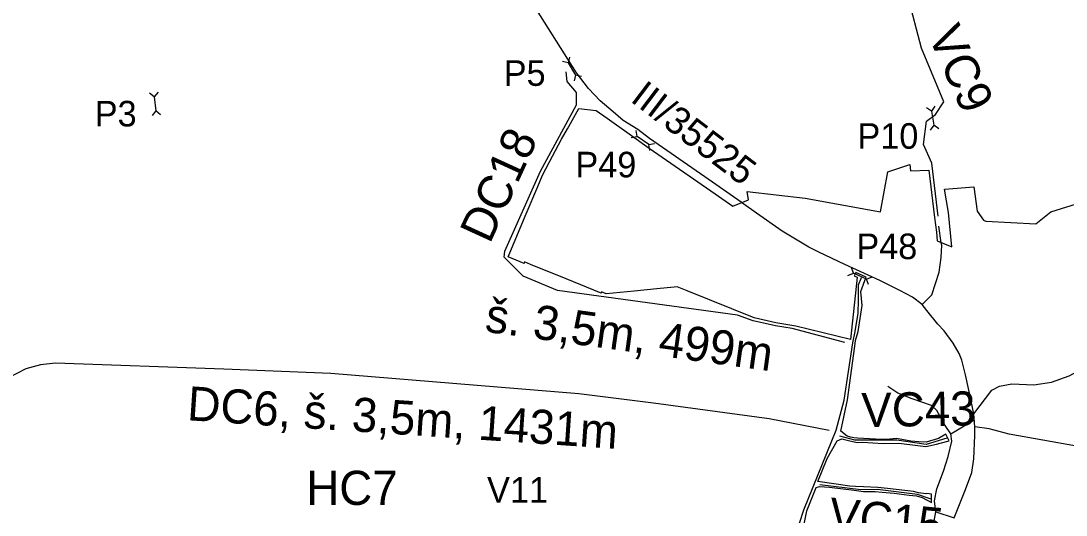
# Model space of a CAD drawing. Extents: x -638669 to -632369, y -1091026 to -1088056.
# Drawn here: x -636112 to -635193, y -1089141 to -1088706 of the extents above; entities that cross this region are included whole.
import ezdxf

# ---------------------------------------------------------------- set-up
doc = ezdxf.new("R2010")
doc.units = 0
for name, color, linetype in [('01_DOPRAVA', 7, 'Continuous'), ('01_DOPRAVA_MIMO_OBVOD', 7, 'Continuous'), ('01_OBVOD PÚ', 7, 'Continuous'), ('03_PC_NÁVRH', 7, 'Continuous'), ('03_PC_OBJEKTY_NÁVRH', 7, 'Continuous'), ('03_PC_OBJEKTY_STAV', 7, 'Continuous'), ('03_PC_POPIS_NÁVRH', 7, 'Continuous'), ('03_PC_POPIS_STAV', 7, 'Continuous'), ('03_PC_STAV', 7, 'Continuous')]:
    doc.layers.add(name, color=color, linetype=linetype)

msp = doc.modelspace()

# ---------------------------------------------------------------- linework, layer by layer
at = {"layer": '01_DOPRAVA'}
for points in [[(-635644.66, -1088718.58), (-635665.58, -1088684.91), (-635674.3, -1088665.29), (-635680.03, -1088638.99), (-635693.11, -1088583.35), (-635700.34, -1088549.68), (-635708.54, -1088514.84), (-635709.97, -1088510.03)], [(-635478.23, -1088866.19), (-635478.71, -1088865.85), (-635510.61, -1088843.52), (-635559.33, -1088809.76), (-635569.65, -1088801.76), (-635582.36, -1088793.88), (-635591.28, -1088786.39), (-635602.56, -1088776.58), (-635612.94, -1088765.82), (-635623.33, -1088751.99), (-635644.66, -1088718.58)], [(-635302.67, -1088901.38), (-635304.79, -1088886.79)]]:
    msp.add_lwpolyline(points, dxfattribs=at)
at = {"layer": '01_DOPRAVA_MIMO_OBVOD'}
for points in [[(-635291.33, -1089143.24), (-635281.53, -1089118.45), (-635275.76, -1089103.47), (-635273.99, -1089091.46), (-635273.18, -1089070.9), (-635273.18, -1089063.45), (-635274.09, -1089051.83), (-635278.86, -1089029.62), (-635281.31, -1089017.61), (-635284.6, -1089004.63), (-635287.12, -1088998.89), (-635292.13, -1088989.85), (-635300.32, -1088979.01), (-635305.81, -1088973), (-635315.3, -1088961.05), (-635319.43, -1088955.73), (-635328.1, -1088949.4), (-635339.09, -1088943.42), (-635356.73, -1088934.6), (-635387.5, -1088920.52), (-635410.49, -1088909.59), (-635419.19, -1088905.26), (-635442.61, -1088891.38), (-635465.19, -1088875.48), (-635478.23, -1088866.19)], [(-635319.43, -1088955.73), (-635311.13, -1088947.31), (-635304.64, -1088927.34), (-635302.92, -1088914.37), (-635302.33, -1088903.69), (-635302.67, -1088901.38)], [(-635274.09, -1089051.83), (-635258.33, -1089031.16), (-635251.47, -1089027.62), (-635240.71, -1089025.61), (-635221.23, -1089026.26), (-635205.73, -1089024.13), (-635190.13, -1089018.41), (-635176.86, -1089011.04), (-635164.81, -1089001.81), (-635156.09, -1088993.24), (-635156.01, -1088993.12)], [(-635294.21, -1089069.4), (-635299.21, -1089062.14), (-635306.66, -1089048.94), (-635311.32, -1089044.61), (-635328.18, -1089038.64), (-635340.93, -1089033.8), (-635349.77, -1089027.84)], [(-635307.37, -1089138.23), (-635308.66, -1089128.55), (-635306.52, -1089117.89), (-635300.88, -1089102.45), (-635296.56, -1089089.37), (-635293.4, -1089075.96), (-635294.21, -1089069.4), (-635273.66, -1089057.3)], [(-635145.56, -1089082.78), (-635169.21, -1089082.73), (-635183.95, -1089080.47), (-635243.03, -1089069.9), (-635260.61, -1089065.14), (-635273.18, -1089063.45)], [(-635338.07, -1089252.85), (-635335.26, -1089238.13), (-635335.41, -1089227.97), (-635332.77, -1089214.03), (-635328.47, -1089200.51), (-635317.9, -1089179.19), (-635314.6, -1089170.56), (-635310.08, -1089152.59), (-635307.37, -1089138.23), (-635291.33, -1089143.24)]]:
    msp.add_lwpolyline(points, dxfattribs=at)
at = {"layer": '01_OBVOD PÚ'}
msp.add_lwpolyline([(-635426.92, -1089166.93), (-635420.92, -1089137.3), (-635412.69, -1089116.75), (-635409.74, -1089115.9), (-635401.11, -1089116.43), (-635379.29, -1089119.09), (-635371.05, -1089120.1), (-635360.9, -1089120.25), (-635354.71, -1089120.84), (-635344.13, -1089121.62), (-635330.91, -1089123.51), (-635324.56, -1089124.1), (-635319.45, -1089125.46), (-635311.18, -1089129.84), (-635311.31, -1089122.66), (-635313.23, -1089122.32), (-635315.71, -1089121.92), (-635316.31, -1089122.4), (-635322.65, -1089121.39), (-635327.26, -1089120.31), (-635349.94, -1089117.72), (-635358.63, -1089116.73), (-635371.04, -1089116.17), (-635378.09, -1089115.85), (-635383.25, -1089115.49), (-635411.38, -1089111.54), (-635402.9, -1089091.33), (-635394.3, -1089075.77), (-635390.24, -1089073.88), (-635384.18, -1089075.32), (-635376.54, -1089077.13), (-635371.84, -1089076.96), (-635353.75, -1089077.9), (-635340.18, -1089077.61), (-635323.29, -1089079.74), (-635316.25, -1089080.62), (-635306.86, -1089078.63), (-635303.6, -1089077.73), (-635295.64, -1089075.55), (-635298.64, -1089069.81), (-635305.27, -1089073.56), (-635315.88, -1089076.79), (-635322.39, -1089076.54), (-635329.42, -1089075.89), (-635341.99, -1089073.71), (-635350.84, -1089074.53), (-635355.38, -1089074.38), (-635376.39, -1089073.41), (-635379.59, -1089073.05), (-635382.56, -1089072.41), (-635385.51, -1089071.48), (-635391.17, -1089067.12), (-635385.06, -1089039.5), (-635378.75, -1088992.32), (-635378.08, -1088987.33), (-635375.83, -1088979.61), (-635372.22, -1088956.67), (-635373.37, -1088944.35), (-635369.95, -1088934.7), (-635368.8, -1088931.63), (-635377.78, -1088927.53), (-635379.28, -1088930.46), (-635376.55, -1088931.71), (-635382.41, -1088986.58), (-635430.69, -1088974.75), (-635448.2, -1088971.89), (-635467.36, -1088967.38), (-635526.12, -1088943.83), (-635534.98, -1088940.28), (-635537.46, -1088940.48), (-635552.7, -1088941.96), (-635572.59, -1088943.89), (-635597.21, -1088946.28), (-635601.37, -1088944.58), (-635601.82, -1088945.69), (-635632.55, -1088933.25), (-635663.85, -1088920.58), (-635669.13, -1088918.22), (-635669.47, -1088919.73), (-635683.6, -1088913.78), (-635678.26, -1088901.16), (-635672.92, -1088888.54), (-635667.69, -1088876.16), (-635657.41, -1088851.85), (-635653.23, -1088841.98), (-635644.46, -1088825.42), (-635636.55, -1088810.49), (-635631.43, -1088801.39), (-635630.22, -1088799.23), (-635621.38, -1088783.51), (-635606.09, -1088785.18), (-635596.56, -1088792.01), (-635577.16, -1088805.79), (-635559.56, -1088818.16), (-635501.46, -1088858.56), (-635486.01, -1088869.3), (-635472.31, -1088863.82), (-635473.26, -1088856.28), (-635422.33, -1088862.1), (-635356.23, -1088874.39), (-635349.74, -1088839.03), (-635330.3, -1088832.56), (-635329.77, -1088838.1), (-635313.7, -1088837.72), (-635308.78, -1088879.13), (-635306.93, -1088892.22), (-635306.36, -1088899.9), (-635293.39, -1088905.1), (-635296.45, -1088874.7), (-635299.78, -1088854.26), (-635274.21, -1088852.38), (-635271.17, -1088873.6), (-635265.61, -1088881.69), (-635263.41, -1088882.51), (-635219.71, -1088884.85), (-635206.48, -1088874.38), (-635179.11, -1088865.65)], dxfattribs=at)
at = {"layer": '03_PC_NÁVRH'}
for points in [[(-635548.27, -1089483.24), (-635540.38, -1089456.77), (-635533.44, -1089442.45), (-635516.92, -1089414.03), (-635511.3, -1089401.47), (-635501.57, -1089371.31), (-635494.01, -1089341.69), (-635489.33, -1089317.95), (-635484.41, -1089308.94), (-635479.38, -1089302.71), (-635457.02, -1089283.85), (-635450.2, -1089272.94), (-635445.04, -1089242.94), (-635427.35, -1089147.99), (-635423.68, -1089136.34), (-635395.14, -1089066.39), (-635387.97, -1089039.81), (-635380.37, -1088989.45), (-635378.51, -1088979.5), (-635375.81, -1088963.45), (-635375.41, -1088952.35), (-635375.42, -1088938.55), (-635372.9, -1088932.07)], [(-635297.96, -1089073.28), (-635316.05, -1089078.74), (-635341.9, -1089075.19), (-635378.69, -1089075.05), (-635392.05, -1089071.41)], [(-635311.72, -1089126.86), (-635323.56, -1089122.98), (-635358.79, -1089118.46), (-635373.55, -1089118.83), (-635409.58, -1089114.49)]]:
    msp.add_lwpolyline(points, dxfattribs=at)
at = {"layer": '03_PC_OBJEKTY_NÁVRH'}
for points in [[(-635384.84, -1088930.13), (-635379.88, -1088928.24), (-635381.77, -1088923.29)], [(-635368.48, -1088933.35), (-635379.88, -1088928.24)], [(-635366.59, -1088938.31), (-635368.48, -1088933.35), (-635363.52, -1088931.46)]]:
    msp.add_lwpolyline(points, dxfattribs=at)
at = {"layer": '03_PC_OBJEKTY_STAV'}
for points in [[(-635629.45, -1088738.14), (-635630.71, -1088743.29), (-635635.86, -1088742.03)], [(-635630.71, -1088743.29), (-635624.22, -1088753.97)], [(-635619.06, -1088755.23), (-635624.22, -1088753.97), (-635625.47, -1088759.12)], [(-635991.32, -1088768.96), (-635994.65, -1088773.09), (-635998.78, -1088769.77)], [(-635994.65, -1088773.09), (-635993.3, -1088785.52)], [(-635308.34, -1088781.45), (-635311.41, -1088785.77), (-635315.74, -1088782.71)], [(-635989.17, -1088788.85), (-635993.3, -1088785.52), (-635996.63, -1088789.65)], [(-635311.41, -1088785.77), (-635309.31, -1088798.09)], [(-635575.4, -1088808.8), (-635570.17, -1088807.9), (-635571.07, -1088802.67)], [(-635304.98, -1088801.16), (-635309.31, -1088798.09), (-635312.38, -1088802.42)], [(-635559.95, -1088815.1), (-635570.17, -1088807.9)], [(-635559.05, -1088820.33), (-635559.95, -1088815.1), (-635554.73, -1088814.2)]]:
    msp.add_lwpolyline(points, dxfattribs=at)
at = {"layer": '03_PC_STAV'}
for points in [[(-635305.52, -1088878.04), (-635311.02, -1088831.43), (-635318.27, -1088815.03), (-635315.85, -1088794.53), (-635307.76, -1088788.74), (-635300.37, -1088777.56), (-635320.14, -1088730.38), (-635332.25, -1088684.22)], [(-635387.45, -1088989.27), (-635433.89, -1088976.97), (-635448.48, -1088974.6), (-635468.24, -1088970.05), (-635481.79, -1088965.04), (-635640.15, -1088943.51), (-635670.28, -1088930.72), (-635687.17, -1088914.25), (-635686.33, -1088908.91), (-635655.19, -1088838.56), (-635623.29, -1088780.2), (-635623.42, -1088769.39), (-635631.5, -1088759.72), (-635632.55, -1088751.14)], [(-635401.37, -1089066.59), (-635454.01, -1089056.2), (-635555.74, -1089042.48), (-635621.42, -1089034.32), (-635839.32, -1089016.44), (-635933.43, -1089012.67), (-636081.59, -1089007.37), (-636094.69, -1089008.96), (-636107.45, -1089012.46), (-636131.51, -1089024.59), (-636151.75, -1089030.3), (-636818.33, -1089074.64)]]:
    msp.add_lwpolyline(points, dxfattribs=at)

# ---------------------------------------------------------------- texts
at = {"layer": '01_DOPRAVA'}
msp.add_text('III/35525', height=24, rotation=322.81591, dxfattribs=at).set_placement((-635576.94, -1088776.62))
at = {"layer": '03_PC_OBJEKTY_NÁVRH'}
for s, p in [('P48', (-635377.36, -1088915.87)), ('V11', (-635702.05, -1089130.09))]:
    msp.add_text(s, height=22.5, dxfattribs=at).set_placement(p)
at = {"layer": '03_PC_OBJEKTY_STAV'}
for s, p in [('P5', (-635687.41, -1088763.46)), ('P3', (-636046.97, -1088799.16)), ('P10', (-635376.39, -1088818.8)), ('P49', (-635624.38, -1088843.96))]:
    msp.add_text(s, height=22.5, dxfattribs=at).set_placement(p)
at = {"layer": '03_PC_POPIS_NÁVRH'}
for s, rotation, p in [('VC43', 0.89108, (-635372.76, -1089063.61)), ('VC15', 354.51502, (-635402.46, -1089155.31))]:
    msp.add_text(s, height=30, rotation=rotation, dxfattribs=at).set_placement(p)
msp.add_text('HC7', height=30, dxfattribs=at).set_placement((-635860.96, -1089132))
at = {"layer": '03_PC_POPIS_STAV'}
for s, rotation, p in [('VC9', 294.11196, (-635314.9, -1088718.58)), ('DC18', 65.40139, (-635699.69, -1088903.18)), ('š. 3,5m, 499m', 352.09399, (-635704.74, -1088979.51)), ('DC6, š. 3,5m, 1431m', 356.17615, (-635966.23, -1089057.48))]:
    msp.add_text(s, height=30, rotation=rotation, dxfattribs=at).set_placement(p)

doc.saveas('drawing.dxf')
